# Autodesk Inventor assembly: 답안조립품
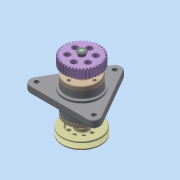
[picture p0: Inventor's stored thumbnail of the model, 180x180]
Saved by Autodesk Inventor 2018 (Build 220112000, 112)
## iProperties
Created: 2023-04
Part Number: 답안조립품
Material: 일반
Document SubType Name: Assembly
Designer: 강의실04
Author: 강의실04
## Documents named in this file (11)
- C:\Users\kimgi\Desktop\730407V1005\답안조립품.iam
- C:\Users\kimgi\Desktop\730407V1005\730407V1005\본체.ipt
- C:\Users\kimgi\Desktop\730407V1005\베어링 6204.ipt
- C:\Users\kimgi\Desktop\730407V1005\축.ipt
- C:\Users\kimgi\Desktop\730407V1005\커버.ipt
- C:\Users\kimgi\Desktop\730407V1005\오일 실 20 32 8.ipt
- C:\Users\kimgi\Desktop\730407V1005\묻힘키 5x5x16.ipt
- C:\Users\kimgi\Desktop\730407V1005\볼트 M4 x 12.ipt
- C:\Users\kimgi\Desktop\730407V1005\v-벨트풀리.ipt
- C:\Users\kimgi\Desktop\730407V1005\스퍼기어.ipt
- C:\Users\kimgi\Desktop\730407V1005\6각 플랜지 너트 M10.ipt
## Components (3 placed, 2 different names)
1. v-벨트풀리:1
2. 6각 플랜지 너트 M10:1
3. 6각 플랜지 너트 M10:2
